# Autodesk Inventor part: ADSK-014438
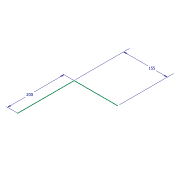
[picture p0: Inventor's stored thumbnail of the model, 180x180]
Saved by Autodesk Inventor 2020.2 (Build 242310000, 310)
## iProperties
Created: 2019-12
Part Number: ADSK-014438
Material: 1.0501 C35
Document SubType Name: Modeling
Designer: lutzd
Density: 7.84 g/cm^3
Appearance: Stahl
Title: skeleton
Author: lutzd
Revision Number: -
VLDS_Profile: Default Part
VLDS_TimeStamp: 2016-07-29
VLDS_FailCnt: 0
VLDS_AcceptCnt: 0
Dimensions: 0x0x0 mm
Mass: 0 kg
DocNumber: ADSK-014438
Folder: 01 - Themengebiete\Simplification\01 - Packaging machine\Parts\
VDS_Category: 3D Komponenten
VDS_NumSchm: Autodesk
VLT_Material: 1.0501 C35
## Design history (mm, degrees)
sketch "Skizze1"
  geometry: L1 (0, 0)-(0, 200); L2 (0, 200)-(155, 200)
  constraints: 4 end point, 1 perpendicular, 1 vertical
  dimensions: "d0" = 200 dimension on L1.start L1.end L1 L2.end L2; "d0" = 200 distance of L1.start L1.end; "d1" = 155 distance of L1.end L2.end
